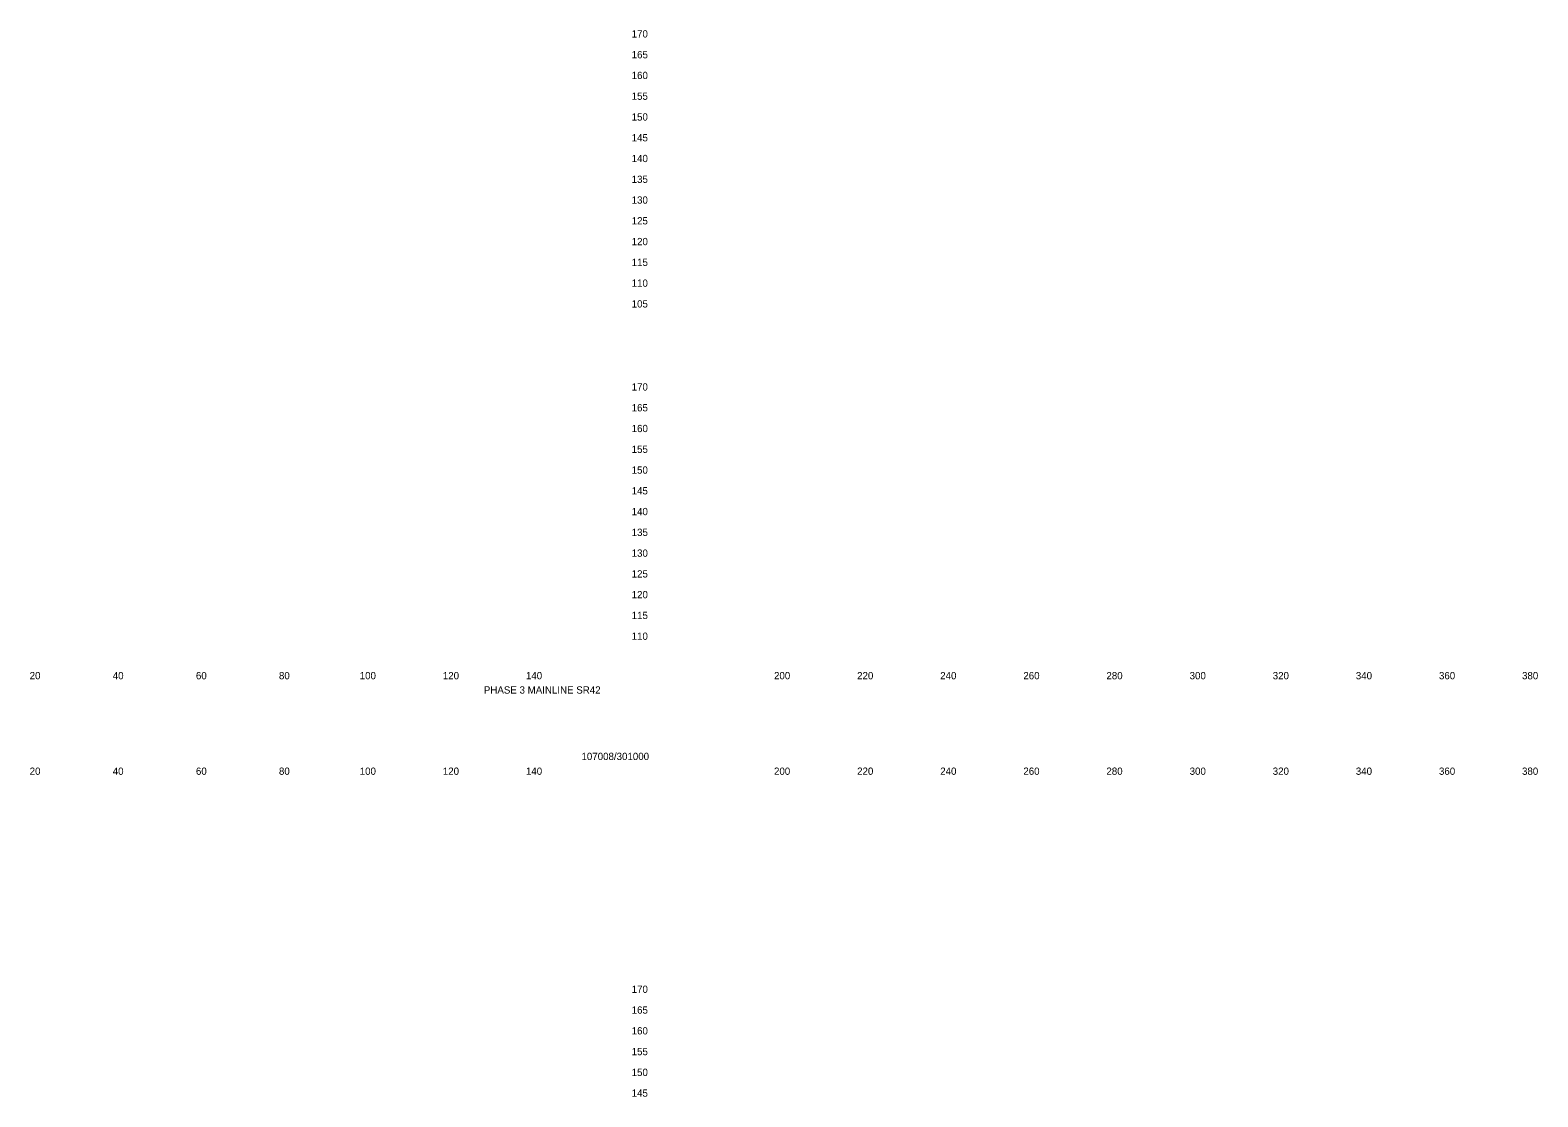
# Model space of a CAD drawing. Extents: x 21281 to 22024, y 6472 to 15198.
# Drawn here: x 21661.4 to 22024.2, y 10284.8 to 10541.6 of the extents above; entities that cross this region are included whole.
import ezdxf

# ---------------------------------------------------------------- set-up
doc = ezdxf.new("R2010")
doc.units = 0
doc.layers.add('Draft_XS_Grid', color=7, linetype='Continuous')
doc.layers.add('Draft_XS_Text', color=7, linetype='Continuous')

msp = doc.modelspace()

# ---------------------------------------------------------------- texts
at = {"layer": 'Draft_XS_Grid'}
for s, p in [('  170  ', (21804.84, 10539.84)), ('  165  ', (21804.84, 10534.84)), ('  160  ', (21804.84, 10529.84)), ('  155  ', (21804.84, 10524.84)), ('  150  ', (21804.84, 10519.84)), ('  145  ', (21804.84, 10514.84)), ('  140  ', (21804.84, 10509.84)), ('  135  ', (21804.84, 10504.84)), ('  130  ', (21804.84, 10499.84)), ('  125  ', (21804.84, 10494.84)), ('  120  ', (21804.84, 10489.84)), ('  115  ', (21804.84, 10484.84)), ('  110  ', (21804.84, 10479.84)), ('  105  ', (21804.84, 10474.84)), ('  170  ', (21804.84, 10454.84)), ('  165  ', (21804.84, 10449.84)), ('  160  ', (21804.84, 10444.84)), ('  155  ', (21804.84, 10439.84)), ('  150  ', (21804.84, 10434.84)), ('  145  ', (21804.84, 10429.84)), ('  140  ', (21804.84, 10424.84)), ('  135  ', (21804.84, 10419.84)), ('  130  ', (21804.84, 10414.84)), ('  125  ', (21804.84, 10409.84)), ('  120  ', (21804.84, 10404.84)), ('  115  ', (21804.84, 10399.84)), ('  110  ', (21804.84, 10394.84)), ('  170  ', (21804.84, 10309.84)), ('  165  ', (21804.84, 10304.84)), ('  160  ', (21804.84, 10299.84)), ('  155  ', (21804.84, 10294.84)), ('  150  ', (21804.84, 10289.84)), ('  145  ', (21804.84, 10284.84))]:
    msp.add_text(s, height=1.75, dxfattribs=at).set_placement(p)
at = {"layer": 'Draft_XS_Text'}
for s, p in [('  20  ', (21659.95, 10385.34)), ('  40  ', (21679.95, 10385.34)), ('  60  ', (21699.97, 10385.34)), ('  80  ', (21719.95, 10385.34)), ('  100  ', (21739.39, 10385.34)), ('  120  ', (21759.39, 10385.34)), ('  140  ', (21779.39, 10385.34)), ('  200  ', (21839.1, 10385.34)), ('  220  ', (21859.1, 10385.34)), ('  240  ', (21879.1, 10385.34)), ('  260  ', (21899.11, 10385.34)), ('  280  ', (21919.1, 10385.34)), ('  300  ', (21939.13, 10385.34)), ('  320  ', (21959.13, 10385.34)), ('  340  ', (21979.13, 10385.34)), ('  360  ', (21999.14, 10385.34)), ('  380  ', (22019.13, 10385.34)), ('PHASE 3 MAINLINE SR42', (21770.57, 10381.89)), ('107008/301000', (21794.06, 10365.9)), ('  20  ', (21659.95, 10362.34)), ('  40  ', (21679.95, 10362.34)), ('  60  ', (21699.97, 10362.34)), ('  80  ', (21719.95, 10362.34)), ('  100  ', (21739.39, 10362.34)), ('  120  ', (21759.39, 10362.34)), ('  140  ', (21779.39, 10362.34)), ('  200  ', (21839.1, 10362.34)), ('  220  ', (21859.1, 10362.34)), ('  240  ', (21879.1, 10362.34)), ('  260  ', (21899.11, 10362.34)), ('  280  ', (21919.1, 10362.34)), ('  300  ', (21939.13, 10362.34)), ('  320  ', (21959.13, 10362.34)), ('  340  ', (21979.13, 10362.34)), ('  360  ', (21999.14, 10362.34)), ('  380  ', (22019.13, 10362.34))]:
    msp.add_text(s, height=1.75, dxfattribs=at).set_placement(p)

doc.saveas('drawing.dxf')
